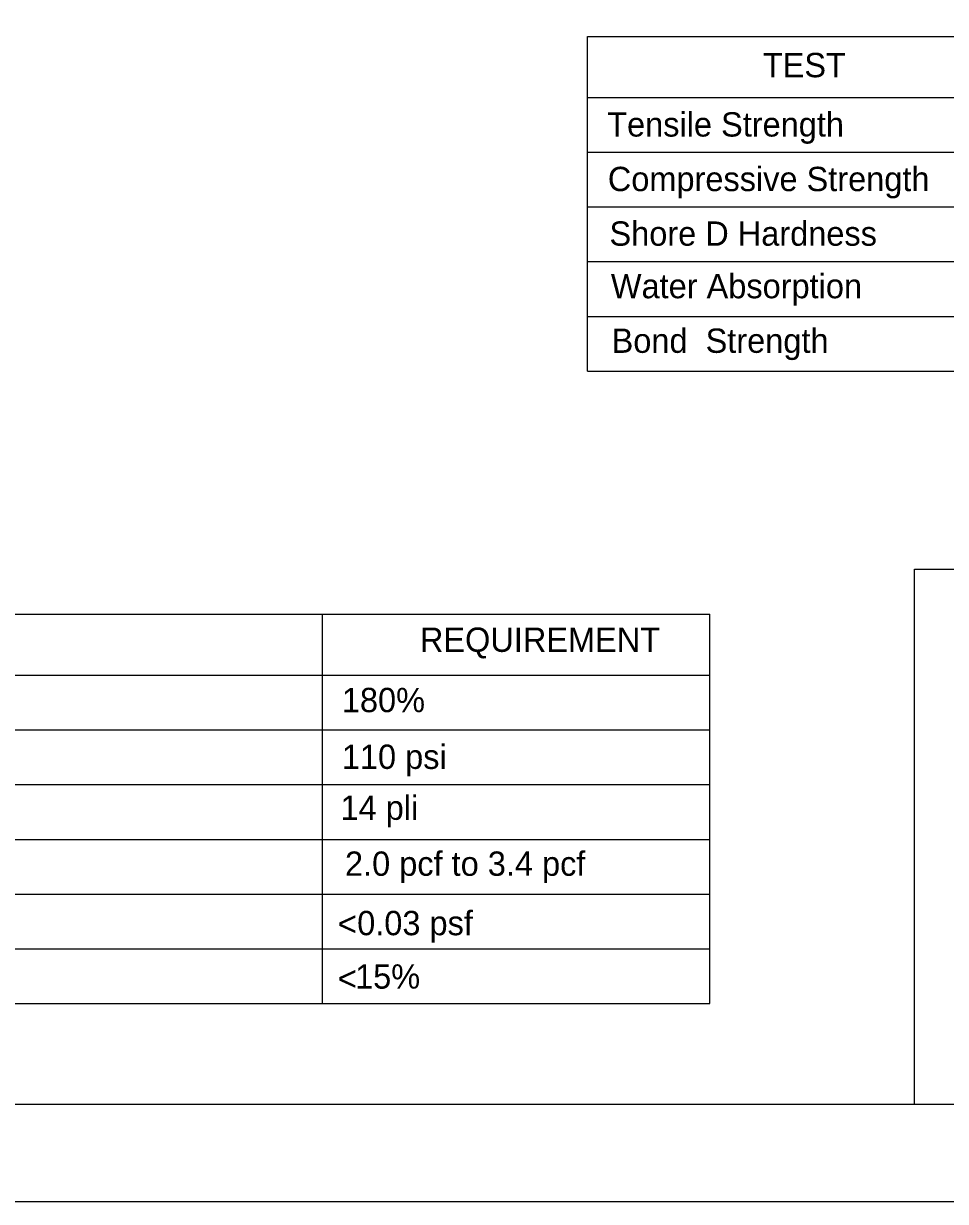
# Model space of a CAD drawing. Extents: x -125.5 to -89.4, y -5.1 to 16.9.
# Drawn here: x -107.48 to -102.74, y -5.07 to 0.99 of the extents above; entities that cross this region are included whole.
import ezdxf

# ---------------------------------------------------------------- set-up
doc = ezdxf.new("R2010")
doc.units = 0
for name, color, linetype in [('BR_BORDER LINES', 7, 'Continuous'), ('BR_TABLE LINES', 7, 'Continuous'), ('BR_TEXT', 7, 'Continuous'), ('Level 31', 7, 'Continuous')]:
    doc.layers.add(name, color=color, linetype=linetype)

msp = doc.modelspace()

# ---------------------------------------------------------------- linework, layer by layer
at = {"layer": 'BR_BORDER LINES'}
for p, q in [((-102.8989, -1.8161), (-97.5337, -1.8161)), ((-102.8989, -4.5661), (-102.8989, -1.8161)), ((-123.6994, -4.5662), (-90.0334, -4.5662))]:
    msp.add_line(p, q, dxfattribs=at)
at = {"layer": 'BR_TABLE LINES'}
for p, q in [((-104.5796, 0.9224), (-99.3257, 0.9224)), ((-104.5796, -0.7981), (-104.5796, 0.9224)), ((-104.5796, 0.6092), (-99.3257, 0.6092)), ((-104.5796, 0.3278), (-99.3257, 0.3278)), ((-104.5796, 0.0463), (-99.3257, 0.0463)), ((-104.5796, -0.2352), (-99.3257, -0.2352)), ((-104.5796, -0.5167), (-99.3257, -0.5167)), ((-104.5796, -0.7981), (-99.3257, -0.7981)), ((-113.8169, -2.0474), (-103.9518, -2.0474)), ((-105.9422, -4.0493), (-105.9422, -2.0474)), ((-103.9518, -4.0493), (-103.9518, -2.0474)), ((-113.8169, -2.3605), (-103.9518, -2.3605)), ((-113.8169, -2.642), (-103.9518, -2.642)), ((-113.8169, -2.9234), (-103.9518, -2.9234)), ((-113.8169, -3.2049), (-103.9518, -3.2049)), ((-113.8169, -3.4864), (-103.9518, -3.4864)), ((-113.8169, -3.7679), (-103.9518, -3.7679)), ((-113.8169, -4.0493), (-103.9518, -4.0493))]:
    msp.add_line(p, q, dxfattribs=at)
at = {"layer": 'Level 31'}
msp.add_lwpolyline([(-125.5328, 16.9339), (-125.5328, -5.0661), (-89.5328, -5.0661), (-89.5328, 16.9339)], dxfattribs=at)

# ---------------------------------------------------------------- texts
at = {"layer": 'BR_TEXT'}
for s, p in [('TEST', (-103.6792, 0.7129)), ('Tensile Strength', (-104.4791, 0.4079)), ('Compressive Strength', (-104.4759, 0.1274)), ('Shore D Hardness', (-104.4674, -0.1532)), ('Water Absorption', (-104.4603, -0.4233)), ('Bond  Strength', (-104.4564, -0.7039)), ('REQUIREMENT', (-105.4421, -2.241)), ('180% ', (-105.8432, -2.551)), ('110 psi ', (-105.8432, -2.8427)), ('14 pli ', (-105.8502, -3.1045)), ('2.0 pcf to 3.4 pcf', (-105.827, -3.3922)), (' 0.03 psf', (-105.8108, -3.6976)), ('<', (-105.8638, -3.7005)), (' 15% ', (-105.8217, -3.9722)), ('<', (-105.8638, -3.9817))]:
    msp.add_text(s, height=0.125, dxfattribs=at).set_placement(p)

doc.saveas('drawing.dxf')
